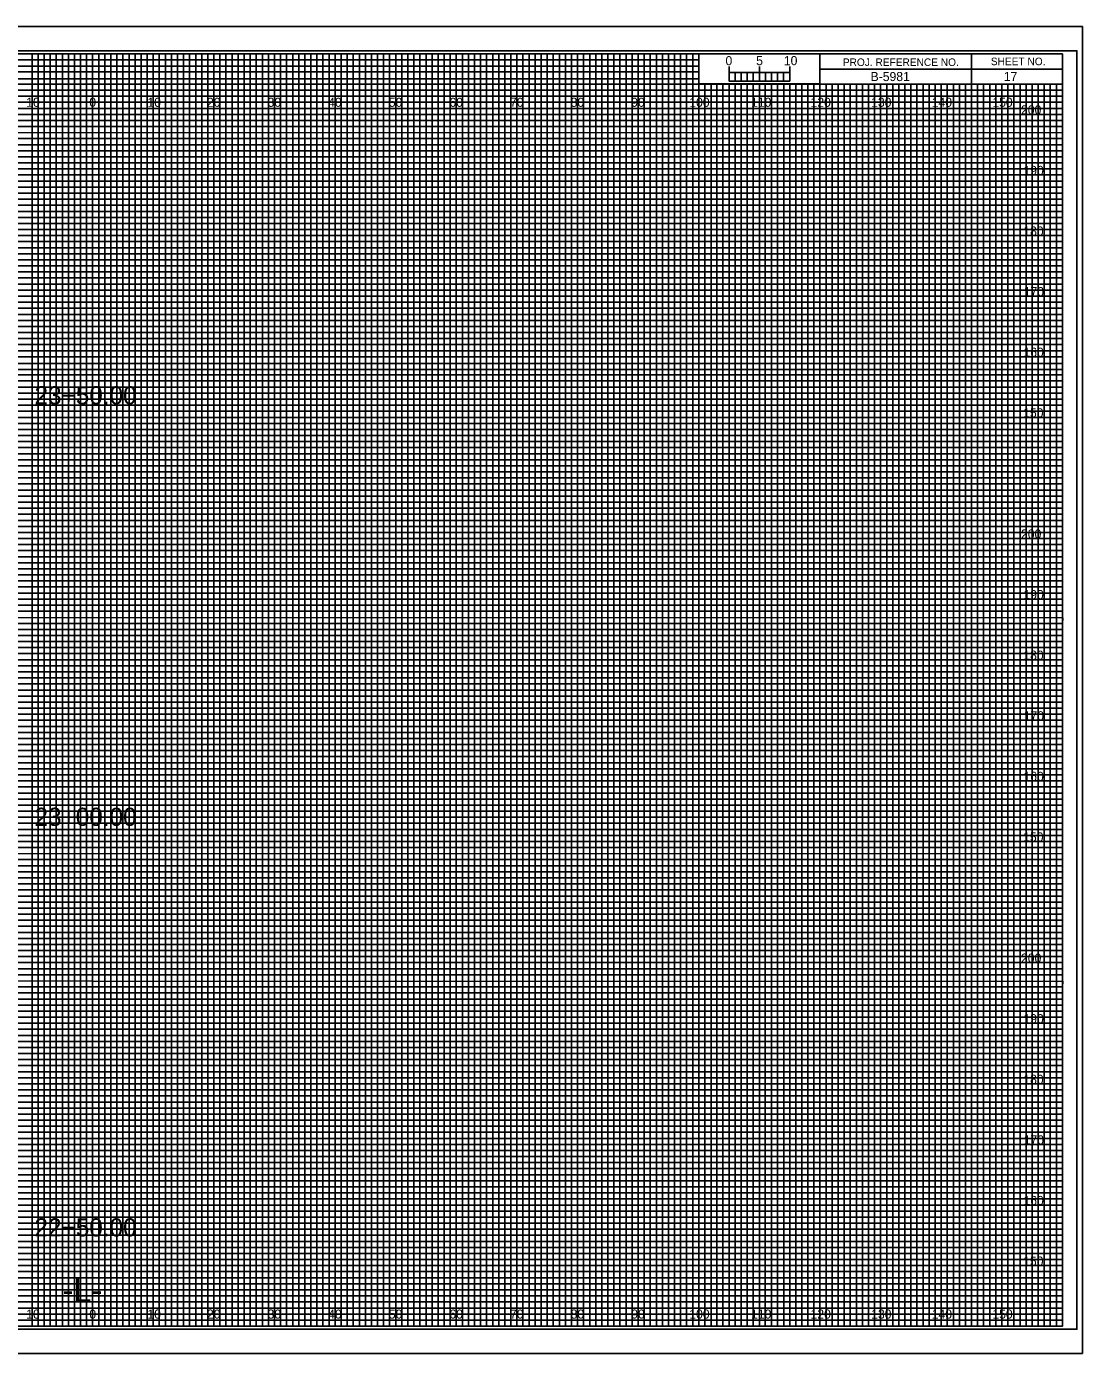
# Model space of a CAD drawing. Extents: x -13 to 323, y -5 to 4174.
# Drawn here: x 149.1 to 323.3, y 2415.5 to 2634.5 of the extents above; entities that cross this region are included whole.
import ezdxf

# ---------------------------------------------------------------- set-up
doc = ezdxf.new("R2010")
doc.units = 0
for name, color, linetype in [('Exist Cross Section Cell', 7, 'Continuous'), ('Exist XS Center Line Elevation Label', 7, 'Continuous'), ('Exist XS Ground Line', 7, 'Continuous'), ('Prop CMT Concrete Structures', 7, 'Continuous'), ('Prop CMT Guardrail Graphics', 7, 'Continuous'), ('Prop CMT Pvmt Course 1', 7, 'Continuous'), ('Prop CMT Pvmt Course 2', 7, 'Continuous'), ('Prop CMT Pvmt Course 3', 7, 'Continuous'), ('Prop CMT Pvmt Surface', 7, 'Continuous'), ('Prop CMT Shld Paved Course 1', 7, 'Continuous'), ('Prop CMT Shld Paved Course 2', 7, 'Continuous'), ('Prop CMT Shld Paved Course 3', 7, 'Continuous'), ('Prop CMT Subgrade Earthwork', 7, 'Continuous'), ('Prop XS Ditch Standard Text', 7, 'Continuous'), ('Prop XS SE Text', 7, 'Continuous'), ('Prop XS Side Slope Text', 7, 'Continuous'), ('Scratch_Level_0', 7, 'Continuous')]:
    doc.layers.add(name, color=color, linetype=linetype)

msp = doc.modelspace()

# ---------------------------------------------------------------- linework, layer by layer
at = {"layer": 'Exist XS Center Line Elevation Label'}
for points in [[(145, 2420), (155, 2420), (155, 2630), (165, 2630), (165, 2420), (175, 2420), (175, 2630), (185, 2630), (185, 2420), (195, 2420), (195, 2630), (205, 2630), (205, 2420), (215, 2420), (215, 2630), (225, 2630), (225, 2420), (235, 2420), (235, 2630), (245, 2630), (245, 2420), (255, 2420), (255, 2630), (259.93, 2630), (260, 2630), (260, 2625), (264.99, 2625), (264.99, 2420), (275, 2420), (275, 2625), (285, 2625), (285, 2420), (295, 2420), (295, 2625), (305, 2625), (305, 2420), (315, 2420), (315, 2625)], [(0, 2625), (275, 2625)], [(0, 2605), (320, 2605), (320, 2615), (0, 2615)], [(0, 2585), (320, 2585), (320, 2595), (0, 2595)], [(0, 2565), (320, 2565), (320, 2575), (0, 2575)], [(0, 2545), (320, 2545), (320, 2555), (0, 2555)], [(0, 2525), (320, 2525), (320, 2535), (0, 2535)], [(0, 2505), (320, 2505), (320, 2515), (0, 2515)], [(0, 2485), (320, 2485), (320, 2495), (0, 2495)], [(0, 2465), (320, 2465), (320, 2475), (0, 2475)], [(0, 2445), (320, 2445), (320, 2455), (0, 2455)], [(0, 2425), (320, 2425), (320, 2435), (0, 2435)]]:
    msp.add_lwpolyline(points, dxfattribs=at)
at = {"layer": 'Exist XS Ground Line'}
for p, q in [((150, 2630), (140, 2630)), ((150, 2420), (150, 2630)), ((170, 2630), (160, 2630)), ((160, 2630), (160, 2420)), ((170, 2420), (170, 2630)), ((190, 2630), (180, 2630)), ((180, 2630), (180, 2420)), ((190, 2420), (190, 2630)), ((210, 2630), (200, 2630)), ((200, 2630), (200, 2420)), ((210, 2420), (210, 2630)), ((230, 2630), (220, 2630)), ((220, 2630), (220, 2420)), ((230, 2420), (230, 2630)), ((250, 2630), (240, 2630)), ((240, 2630), (240, 2420)), ((250, 2420), (250, 2630)), ((260, 2630), (260, 2420)), ((270, 2420), (270, 2625)), ((290, 2625), (280, 2625)), ((280, 2625), (280, 2420)), ((290, 2420), (290, 2625)), ((310, 2625), (300, 2625)), ((300, 2625), (300, 2420)), ((310, 2420), (310, 2625)), ((160, 2420), (150, 2420)), ((180, 2420), (170, 2420)), ((200, 2420), (190, 2420)), ((220, 2420), (210, 2420)), ((240, 2420), (230, 2420)), ((260, 2420), (250, 2420)), ((280, 2420), (270, 2420)), ((300, 2420), (290, 2420)), ((320, 2420), (310, 2420)), ((320, 2420), (320, 2420))]:
    msp.add_line(p, q, dxfattribs=at)
for points in [[(0, 2620), (320, 2620), (320, 2610), (0, 2610)], [(0, 2600), (320, 2600), (320, 2590), (0, 2590)], [(0, 2580), (320, 2580), (320, 2570), (0, 2570)], [(0, 2560), (320, 2560), (320, 2550), (0, 2550)], [(0, 2540), (320, 2540), (320, 2530), (0, 2530)], [(0, 2520), (320, 2520), (320, 2510), (0, 2510)], [(0, 2500), (320, 2500), (320, 2490), (0, 2490)], [(0, 2480), (320, 2480), (320, 2470), (0, 2470)], [(0, 2460), (320, 2460), (320, 2450), (0, 2450)], [(0, 2440), (320, 2440), (320, 2430), (0, 2430)]]:
    msp.add_lwpolyline(points, dxfattribs=at)
at = {"layer": 'Prop CMT Pvmt Course 1'}
for p, q in [((323.3, 2634.5), (-13.4, 2634.5)), ((-13.4, 2415.5), (323.3, 2415.5))]:
    msp.add_line(p, q, dxfattribs=at)
at = {"layer": 'Prop CMT Pvmt Course 2'}
msp.add_lwpolyline([(-13.4, 2415.5), (323.3, 2415.5), (323.3, 2634.5), (-13.4, 2634.5)], close=True, dxfattribs=at)
at = {"layer": 'Prop CMT Pvmt Course 3'}
msp.add_lwpolyline([(-10.8, 2419.5), (322.4, 2419.5), (322.4, 2630.5), (-10.8, 2630.5)], close=True, dxfattribs=at)
at = {"layer": 'Prop CMT Shld Paved Course 1'}
for p, q in [((305, 2630), (305, 2625)), ((305, 2625), (305, 2630)), ((280, 2627.5), (280, 2625)), ((320, 2627.49), (280, 2627.49)), ((280, 2625), (320, 2625))]:
    msp.add_line(p, q, dxfattribs=at)
for points in [[(320, 2630), (0, 2630), (0, 2420), (320, 2420)], [(280, 2630), (260, 2630), (260, 2625.03), (280, 2625.03)], [(320, 2630), (280, 2630), (280, 2625), (320, 2625)]]:
    msp.add_lwpolyline(points, close=True, dxfattribs=at)
at = {"layer": 'Prop CMT Shld Paved Course 2'}
for p, q in [((267, 2625), (266.01, 2625)), ((266.01, 2625), (266.01, 2420)), ((267, 2420), (267, 2625)), ((269, 2625), (268, 2625)), ((268, 2625), (268, 2420)), ((269, 2420), (269, 2625)), ((266.01, 2420), (265, 2420)), ((268, 2420), (267, 2420))]:
    msp.add_line(p, q, dxfattribs=at)
for points in [[(150, 2420), (151, 2420), (151, 2630), (152, 2630), (152, 2420)], [(152, 2420), (153, 2420), (153, 2630), (154, 2630), (154, 2420)], [(155, 2420), (156, 2420), (156, 2630), (157, 2630), (157, 2420)], [(157, 2420), (158, 2420), (158, 2630), (159, 2630), (159, 2420)], [(160, 2420), (161, 2420), (161, 2630), (162, 2630), (162, 2420)], [(162, 2420), (163, 2420), (163, 2630), (164, 2630), (164, 2420)], [(165, 2420), (166, 2420), (166, 2630), (167, 2630), (167, 2420)], [(167, 2420), (168, 2420), (168, 2630), (169, 2630), (169, 2420)], [(170, 2420), (171, 2420), (171, 2630), (172, 2630), (172, 2420)], [(172, 2420), (173, 2420), (173, 2630), (174, 2630), (174, 2420)], [(175, 2420), (176, 2420), (176, 2630), (177, 2630), (177, 2420)], [(177, 2420), (178, 2420), (178, 2630), (179, 2630), (179, 2420)], [(180, 2420), (181, 2420), (181, 2630), (182, 2630), (182, 2420)], [(182, 2420), (183, 2420), (183, 2630), (184, 2630), (184, 2420)], [(185, 2420), (186, 2420), (186, 2630), (187, 2630), (187, 2420)], [(187, 2420), (188, 2420), (188, 2630), (189, 2630), (189, 2420)], [(190, 2420), (191, 2420), (191, 2630), (192, 2630), (192, 2420)], [(192, 2420), (193, 2420), (193, 2630), (194, 2630), (194, 2420)], [(195, 2420), (196, 2420), (196, 2630), (197, 2630), (197, 2420)], [(197, 2420), (198, 2420), (198, 2630), (199, 2630), (199, 2420)], [(200, 2420), (201, 2420), (201, 2630), (202, 2630), (202, 2420)], [(202, 2420), (203, 2420), (203, 2630), (204, 2630), (204, 2420)], [(205, 2420), (206, 2420), (206, 2630), (207, 2630), (207, 2420)], [(207, 2420), (208, 2420), (208, 2630), (209, 2630), (209, 2420)], [(210, 2420), (211, 2420), (211, 2630), (212, 2630), (212, 2420)], [(212, 2420), (213, 2420), (213, 2630), (214, 2630), (214, 2420)], [(215, 2420), (216, 2420), (216, 2630), (217, 2630), (217, 2420)], [(217, 2420), (218, 2420), (218, 2630), (219, 2630), (219, 2420)], [(220, 2420), (221, 2420), (221, 2630), (222, 2630), (222, 2420)], [(222, 2420), (223, 2420), (223, 2630), (224, 2630), (224, 2420)], [(225, 2420), (226, 2420), (226, 2630), (227, 2630), (227, 2420)], [(227, 2420), (228, 2420), (228, 2630), (229, 2630), (229, 2420)], [(230, 2420), (231, 2420), (231, 2630), (232, 2630), (232, 2420)], [(232, 2420), (233, 2420), (233, 2630), (234, 2630), (234, 2420)], [(235, 2420), (236, 2420), (236, 2630), (237, 2630), (237, 2420)], [(237, 2420), (238, 2420), (238, 2630), (239, 2630), (239, 2420)], [(240, 2420), (241, 2420), (241, 2630), (242, 2630), (242, 2420)], [(242, 2420), (243, 2420), (243, 2630), (244, 2630), (244, 2420)], [(245, 2420), (246, 2420), (246, 2630), (247, 2630), (247, 2420)], [(247, 2420), (248, 2420), (248, 2630), (249, 2630), (249, 2420)], [(250, 2420), (251, 2420), (251, 2630), (252, 2630), (252, 2420)], [(252, 2420), (253, 2420), (253, 2630), (254, 2630), (254, 2420)], [(255, 2420), (256, 2420), (256, 2630), (257, 2630), (257, 2420)], [(257, 2420), (258, 2420), (258, 2630), (259, 2630), (259, 2420)], [(260, 2420), (261, 2420), (261, 2625), (262.02, 2625), (262.02, 2420)], [(262, 2420), (263, 2420), (263, 2625), (263.99, 2625), (263.99, 2420)], [(270, 2420), (270.98, 2420), (270.98, 2625), (272, 2625), (272, 2420)], [(272, 2420), (273, 2420), (273, 2625), (274.05, 2625), (274.05, 2420)], [(275, 2420), (276, 2420), (276, 2625), (277, 2625), (277, 2420)], [(277, 2420), (278, 2420), (278, 2625), (279, 2625), (279, 2420)], [(280, 2420), (281, 2420), (281, 2625), (282, 2625), (282, 2420)], [(282, 2420), (283, 2420), (283, 2625), (284, 2625), (284, 2420)], [(285, 2420), (286, 2420), (286, 2625), (287, 2625), (287, 2420)], [(287, 2420), (288, 2420), (288, 2625), (289, 2625), (289, 2420)], [(290, 2420), (291, 2420), (291, 2625), (292, 2625), (292, 2420)], [(292, 2420), (293, 2420), (293, 2625), (294, 2625), (294, 2420)], [(295, 2420), (296, 2420), (296, 2625), (297, 2625), (297, 2420)], [(297, 2420), (298, 2420), (298, 2625), (299, 2625), (299, 2420)], [(300, 2420), (301, 2420), (301, 2625), (302, 2625), (302, 2420)], [(302, 2420), (303, 2420), (303, 2625), (304, 2625), (304, 2420)], [(305, 2420), (306, 2420), (306, 2625), (307, 2625), (307, 2420)], [(307, 2420), (308, 2420), (308, 2625), (309, 2625), (309, 2420)], [(310, 2420), (311, 2420), (311, 2625), (312, 2625), (312, 2420)], [(312, 2420), (313, 2420), (313, 2625), (314, 2625), (314, 2420)], [(315, 2420), (316, 2420), (316, 2625), (317, 2625), (317, 2420)], [(317, 2420), (318, 2420), (318, 2625), (319, 2625), (319, 2420)]]:
    msp.add_lwpolyline(points, dxfattribs=at)
at = {"layer": 'Prop CMT Shld Paved Course 3'}
for p, q in [((265, 2625.49), (265, 2627.9)), ((265, 2626.9), (265, 2627.9)), ((270, 2625.49), (270, 2627.9)), ((275, 2625.49), (275, 2627.9)), ((275, 2626.9), (275, 2627.9))]:
    msp.add_line(p, q, dxfattribs=at)
for points in [[(275, 2626.9), (265, 2626.9), (265, 2625.49), (275, 2625.49)], [(265, 2626.9), (266, 2626.9), (266, 2625.49), (265, 2625.49)], [(267, 2626.9), (268, 2626.9), (268, 2625.49), (267, 2625.49)], [(269, 2626.9), (270, 2626.9), (270, 2625.49), (269, 2625.49)], [(271, 2626.9), (272, 2626.9), (272, 2625.49), (271, 2625.49)], [(273, 2626.9), (274, 2626.9), (274, 2625.49), (273, 2625.49)]]:
    msp.add_lwpolyline(points, close=True, dxfattribs=at)
at = {"layer": 'Prop CMT Subgrade Earthwork'}
for p, q in [((150, 2420), (150, 2630)), ((160, 2420), (160, 2630)), ((170, 2420), (170, 2630)), ((180, 2420), (180, 2630)), ((190, 2420), (190, 2630)), ((200, 2420), (200, 2630)), ((210, 2420), (210, 2630)), ((220, 2420), (220, 2630)), ((230, 2420), (230, 2630)), ((240, 2420), (240, 2630)), ((250, 2420), (250, 2630)), ((260, 2420), (260, 2624.69)), ((270, 2420), (270, 2624.69)), ((280, 2420), (280, 2624.69)), ((290, 2420), (290, 2624.69)), ((300, 2420), (300, 2624.69)), ((310, 2420), (310, 2624.69)), ((0, 2620), (320, 2620)), ((0, 2610), (320, 2610)), ((0, 2600), (320, 2600)), ((0, 2590), (320, 2590)), ((0, 2580), (320, 2580)), ((0, 2570), (320, 2570)), ((0, 2560), (320, 2560)), ((0, 2550), (320, 2550)), ((0, 2540), (320, 2540)), ((0, 2530), (320, 2530)), ((0, 2520), (320, 2520)), ((0, 2510), (320, 2510)), ((0, 2500), (320, 2500)), ((0, 2490), (320, 2490)), ((0, 2480), (320, 2480)), ((0, 2470), (320, 2470)), ((0, 2460), (320, 2460)), ((0, 2450), (320, 2450)), ((0, 2440), (320, 2440)), ((0, 2430), (320, 2430))]:
    msp.add_line(p, q, dxfattribs=at)
at = {"layer": 'Scratch_Level_0'}
for p, q in [((0, 2629), (260, 2629)), ((260, 2629), (260, 2627.98)), ((260, 2627.98), (0, 2627.98)), ((0, 2627), (260, 2627)), ((260, 2625.89), (0, 2625.89)), ((260, 2627), (260, 2625.89)), ((0, 2624), (320, 2624))]:
    msp.add_line(p, q, dxfattribs=at)
for points in [[(0, 2623), (270, 2623), (320, 2623), (320, 2622), (0, 2622)], [(0, 2621), (320, 2621), (320, 2619), (0, 2619)], [(0, 2618), (320, 2618), (320, 2617), (0, 2616.98)], [(0, 2616), (320, 2616), (320, 2614), (0, 2614)], [(0, 2613), (320, 2613), (320, 2612), (0, 2612)], [(0, 2611), (320, 2611), (320, 2609), (0, 2609)], [(0, 2608), (320, 2608), (320, 2607), (0, 2607)], [(0, 2606), (320, 2606), (320, 2604), (0, 2604)], [(0, 2603), (320, 2603), (320, 2602), (0, 2602)], [(0, 2601), (320, 2601), (320, 2599), (0, 2599)], [(0, 2598), (320, 2598), (320, 2597), (0, 2597)], [(0, 2596), (320, 2596), (320, 2593.95), (320, 2593), (320, 2592), (0, 2592)], [(0, 2594), (320, 2594), (320, 2593), (0, 2593)], [(0, 2591), (320, 2591), (320, 2589), (0, 2589.03)], [(0, 2589.03), (320, 2589), (320, 2588), (0, 2588)], [(0, 2587), (320, 2587), (320, 2586), (0, 2586)], [(0, 2584), (320, 2584), (320, 2583), (0, 2583)], [(0, 2582), (320, 2582), (320, 2581), (0, 2581)], [(-0.07, 2578.89), (320, 2578.89), (320, 2577.88), (-0.07, 2577.88)], [(0, 2577), (320, 2577), (320, 2576), (0, 2576)], [(0, 2574), (320, 2574), (320, 2573), (0, 2573)], [(0, 2572), (320, 2572), (320, 2571), (0, 2571)], [(0, 2569), (320, 2569), (320, 2568), (0, 2568)], [(0, 2567), (320, 2567), (320, 2566), (0, 2566)], [(0, 2564), (320, 2564), (320, 2563), (0, 2563)], [(0, 2562), (320, 2562), (320, 2561), (0, 2561)], [(0, 2559), (320, 2559), (319.99, 2557.98), (0, 2558)], [(0, 2557), (320, 2557), (320, 2556), (0, 2556)], [(0, 2554), (320, 2554), (320, 2553), (0, 2553)], [(0, 2552), (320, 2552), (320, 2551), (0, 2551)], [(0, 2549), (320, 2549), (320, 2548), (0, 2548)], [(0, 2547), (320, 2547), (320, 2546), (0, 2546)], [(0, 2544), (320, 2544), (320, 2543), (0, 2543)], [(0, 2542), (320, 2542), (320, 2541), (0, 2541)], [(0, 2539), (320, 2539), (320, 2538), (0, 2538)], [(0, 2536.99), (320.07, 2536.91), (320, 2536), (0, 2536)], [(0, 2534), (320, 2534), (320, 2533), (0, 2533)], [(0, 2532), (320, 2532), (320, 2531), (0, 2531)], [(0, 2529), (320, 2529), (320, 2528), (0, 2528)], [(0, 2527), (320, 2527), (320, 2526), (0, 2526)], [(0, 2524), (320, 2524), (320, 2523), (0, 2523)], [(0, 2522), (320, 2522), (320, 2521), (0, 2521)], [(0, 2519), (320, 2519), (320, 2518), (0, 2518)], [(0, 2517), (320, 2517), (320, 2516), (0, 2516)], [(0, 2514), (320, 2514), (320, 2513), (0, 2513)], [(0, 2512), (320, 2512), (320, 2511), (0, 2511)], [(0, 2509), (320, 2509), (320, 2508), (0, 2508)], [(0, 2507), (320, 2507), (320, 2506), (0, 2506)], [(0, 2504), (320, 2504), (320, 2503), (0, 2503)], [(0, 2502), (320, 2502), (320, 2501), (0, 2501)], [(0, 2499), (320, 2499), (319.99, 2497.98), (0, 2498)], [(0, 2497), (320, 2497), (320, 2496), (0, 2496)], [(0, 2494), (320, 2494), (320, 2493), (0, 2493)], [(0, 2492), (320, 2492), (320, 2491), (0, 2491)], [(0, 2489), (320, 2489), (320, 2488), (0, 2488)], [(0, 2487), (320, 2487), (320, 2486), (0, 2486)], [(0, 2484), (320, 2484), (320, 2483), (0, 2483)], [(0, 2482), (320, 2482), (320, 2481), (0, 2481)], [(0, 2479), (320, 2479), (320, 2478), (0, 2478)], [(0, 2476.99), (320.07, 2476.91), (320, 2476), (0, 2476)], [(0, 2474), (320, 2474), (320, 2473), (0, 2473)], [(0, 2472), (320, 2472), (320, 2471), (0, 2471)], [(0, 2469), (320, 2469), (320, 2468), (0, 2468)], [(0, 2467), (320, 2467), (320, 2466), (0, 2466)], [(0, 2464), (320, 2464), (320, 2463), (0, 2463)], [(0, 2462), (320, 2462), (320, 2461), (0, 2461)], [(0, 2459), (320, 2459), (320, 2458), (0, 2458)], [(0, 2457), (320, 2457), (320, 2456), (0, 2456)], [(0, 2454), (320, 2454), (320, 2453), (0, 2453)], [(0, 2452), (320, 2452), (320, 2451), (0, 2451)], [(0, 2449), (320, 2449), (320, 2448), (0, 2448)], [(0, 2447), (320, 2447), (320, 2446), (0, 2446)], [(0, 2444), (320, 2444), (320, 2443), (0, 2443)], [(0, 2442), (320, 2442), (320, 2441), (0, 2441)], [(0, 2439), (320, 2439), (320, 2438), (0, 2438)], [(0, 2437), (320, 2437), (320, 2436), (0, 2436)], [(0, 2434), (320, 2434), (320, 2433), (0, 2433)], [(0, 2432), (320, 2432), (320, 2431), (0, 2431)], [(0, 2429), (320, 2429), (320, 2428), (0, 2428)], [(0, 2427), (320, 2427), (320, 2426), (0, 2426)], [(0, 2424), (320, 2424), (320, 2423), (0, 2423)], [(0, 2422), (320, 2422), (320, 2421), (0, 2421)]]:
    msp.add_lwpolyline(points, dxfattribs=at)

# ---------------------------------------------------------------- texts
at = {"layer": 'Exist Cross Section Cell'}
for s, p in [('10', (149.04, 2621.25)), ('0', (159.45, 2621.25)), ('0', (159.45, 2621.25)), ('10', (169.04, 2621.25)), ('20', (178.86, 2621.25)), ('30', (188.86, 2621.25)), ('40', (198.86, 2621.25)), ('50', (208.86, 2621.25)), ('60', (218.86, 2621.25)), ('70', (228.86, 2621.25)), ('80', (238.86, 2621.25)), ('90', (248.86, 2621.25)), ('100', (258.44, 2621.25)), ('110', (268.62, 2621.25)), ('120', (278.44, 2621.25)), ('130', (288.44, 2621.25)), ('140', (298.44, 2621.25)), ('150', (308.44, 2621.25)), ('10', (149.04, 2421.25)), ('0', (159.45, 2421.25)), ('0', (159.45, 2421.25)), ('10', (169.04, 2421.25)), ('20', (178.86, 2421.25)), ('30', (188.86, 2421.25)), ('40', (198.86, 2421.25)), ('50', (208.86, 2421.25)), ('60', (218.86, 2421.25)), ('70', (228.86, 2421.25)), ('80', (238.86, 2421.25)), ('90', (248.86, 2421.25)), ('100', (258.44, 2421.25)), ('110', (268.62, 2421.25)), ('120', (278.44, 2421.25)), ('130', (288.44, 2421.25)), ('140', (298.44, 2421.25)), ('150', (308.44, 2421.25))]:
    msp.add_text(s, height=1.5, dxfattribs=at).set_placement(p)
at = {"layer": 'Prop CMT Concrete Structures'}
for s, p in [('23+50.00', (150.41, 2572.14)), ('23+00.00', (150.41, 2502.57)), ('22+50.00', (150.41, 2434.81))]:
    msp.add_text(s, height=3, dxfattribs=at).set_placement(p)
at = {"layer": 'Prop CMT Guardrail Graphics'}
for s, p in [('200', (313.17, 2620)), ('190', (313.57, 2610)), ('180', (313.55, 2600)), ('170', (313.61, 2590)), ('160', (313.57, 2580)), ('150', (313.52, 2570)), ('200', (313.17, 2550)), ('190', (313.57, 2540)), ('180', (313.55, 2530)), ('170', (313.61, 2520)), ('160', (313.57, 2510)), ('150', (313.52, 2500)), ('200', (313.17, 2480)), ('190', (313.57, 2470)), ('180', (313.55, 2460)), ('170', (313.61, 2450)), ('160', (313.57, 2440)), ('150', (313.52, 2430))]:
    msp.add_text(s, height=1.5, dxfattribs=at).set_placement(p)
at = {"layer": 'Prop CMT Pvmt Surface'}
for s, p in [('5', (269.47, 2628.12)), ('10', (274.04, 2628.12))]:
    msp.add_text(s, height=1.5, dxfattribs=at).set_placement(p)
at = {"layer": 'Prop CMT Shld Paved Course 1'}
for s, p in [('PROJ. REFERENCE NO.', (283.77, 2627.99)), ('SHEET NO.', (308.19, 2628.12))]:
    msp.add_text(s, height=1.25, dxfattribs=at).set_placement(p)
at = {"layer": 'Prop CMT Shld Paved Course 3'}
msp.add_text('0', height=1.5, dxfattribs=at).set_placement((264.41, 2628.12))
at = {"layer": 'Prop XS Ditch Standard Text'}
msp.add_text('-L-', height=4, dxfattribs=at).set_placement((155.06, 2424))
at = {"layer": 'Prop XS SE Text'}
msp.add_text(' B-5981', height=1.5, dxfattribs=at).set_placement((287.79, 2625.5))
at = {"layer": 'Prop XS Side Slope Text'}
msp.add_text('17', height=1.5, dxfattribs=at).set_placement((310.32, 2625.5))

doc.saveas('drawing.dxf')
